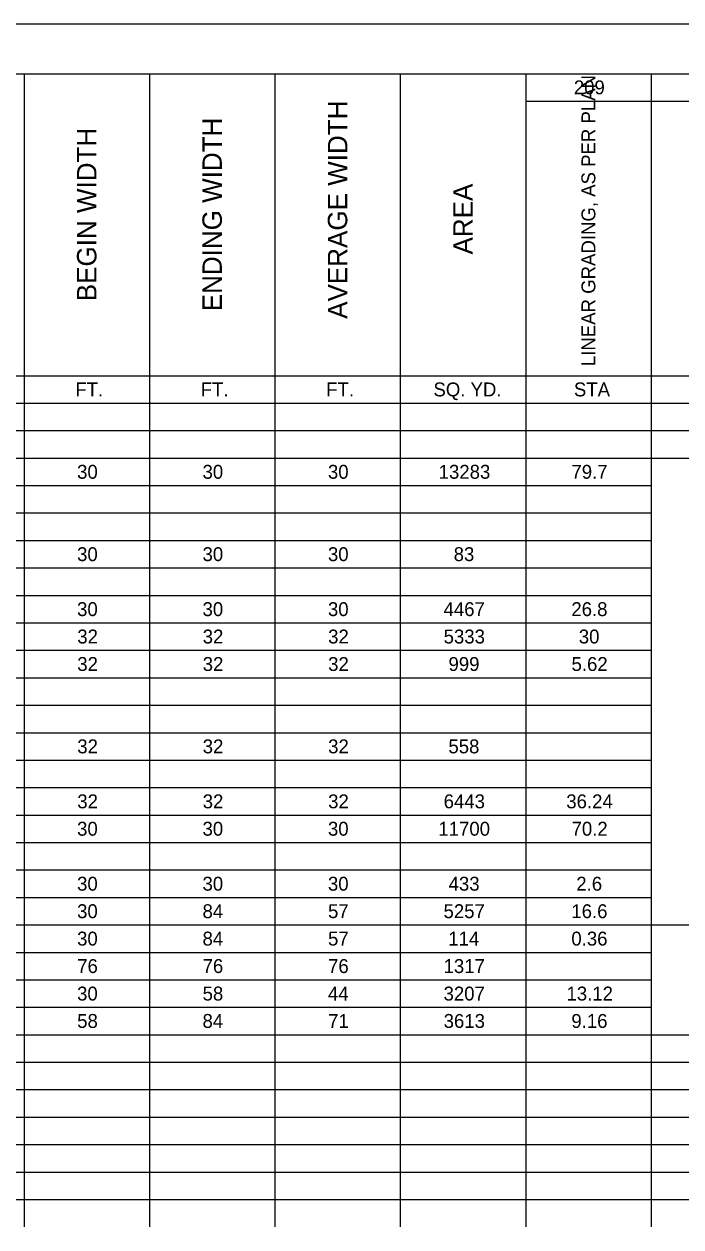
# Model space of a CAD drawing. Extents: x 0 to 34, y 0 to 22.
# Drawn here: x 13.03 to 19.65, y 9.88 to 22 of the extents above; entities that cross this region are included whole.
import ezdxf

# ---------------------------------------------------------------- set-up
doc = ezdxf.new("R2010")
doc.units = 0
for name, color, linetype in [('SH_Border', 7, 'Continuous'), ('SH_Cut_Line', 7, 'Continuous'), ('SH_Text', 7, 'Continuous')]:
    doc.layers.add(name, color=color, linetype=linetype)

msp = doc.modelspace()

# ---------------------------------------------------------------- linework, layer by layer
at = {"layer": 'SH_Border'}
msp.add_lwpolyline([(1.5, 21.5), (33.5, 21.5), (33.5, 0.5), (1.5, 0.5)], close=True, dxfattribs=at)
at = {"layer": 'SH_Cut_Line'}
msp.add_lwpolyline([(0, 0), (34, 0), (34, 22), (0, 22)], close=True, dxfattribs=at)
at = {"layer": 'SH_Text'}
for p, q in [((8.427, 21.5), (13.026, 21.5)), ((13.026, 21.5), (15.556, 21.5)), ((13.026, 21.5), (13.026, 21.223)), ((14.291, 21.5), (14.291, 21.223)), ((15.556, 21.5), (23.145, 21.5)), ((15.556, 21.5), (15.556, 21.223)), ((16.821, 21.5), (16.821, 21.223)), ((18.086, 21.5), (18.086, 21.223)), ((19.351, 21.5), (19.351, 21.223)), ((13.026, 21.223), (13.026, 20.947)), ((14.291, 21.223), (14.291, 20.947)), ((15.556, 21.223), (15.556, 20.947)), ((16.821, 21.223), (16.821, 20.947)), ((18.086, 21.223), (23.145, 21.223)), ((18.086, 21.223), (18.086, 20.947)), ((19.351, 21.223), (19.351, 20.947)), ((13.026, 20.947), (13.026, 20.67)), ((14.291, 20.947), (14.291, 20.67)), ((15.556, 20.947), (15.556, 20.67)), ((16.821, 20.947), (16.821, 20.67)), ((18.086, 20.947), (18.086, 20.67)), ((19.351, 20.947), (19.351, 20.67)), ((13.026, 20.67), (13.026, 20.393)), ((14.291, 20.67), (14.291, 20.393)), ((15.556, 20.67), (15.556, 20.393)), ((16.821, 20.67), (16.821, 20.393)), ((18.086, 20.67), (18.086, 20.393)), ((19.351, 20.67), (19.351, 20.393)), ((13.026, 20.393), (13.026, 20.116)), ((14.291, 20.393), (14.291, 20.116)), ((15.556, 20.393), (15.556, 20.116)), ((16.821, 20.393), (16.821, 20.116)), ((18.086, 20.393), (18.086, 20.116)), ((19.351, 20.393), (19.351, 20.116)), ((13.026, 20.116), (13.026, 19.84)), ((14.291, 20.116), (14.291, 19.84)), ((15.556, 20.116), (15.556, 19.84)), ((16.821, 20.116), (16.821, 19.84)), ((18.086, 20.116), (18.086, 19.84)), ((19.351, 20.116), (19.351, 19.84)), ((13.026, 19.84), (13.026, 19.563)), ((14.291, 19.84), (14.291, 19.563)), ((15.556, 19.84), (15.556, 19.563)), ((16.821, 19.84), (16.821, 19.563)), ((18.086, 19.84), (18.086, 19.563)), ((19.351, 19.84), (19.351, 19.563)), ((13.026, 19.563), (13.026, 19.01)), ((14.291, 19.563), (14.291, 19.01)), ((15.556, 19.563), (15.556, 19.01)), ((16.821, 19.563), (16.821, 19.01)), ((18.086, 19.563), (18.086, 19.01)), ((19.351, 19.563), (19.351, 19.01)), ((13.026, 19.01), (13.026, 18.18)), ((14.291, 19.01), (14.291, 18.18)), ((15.556, 19.01), (15.556, 18.18)), ((16.821, 19.01), (16.821, 18.18)), ((18.086, 19.01), (18.086, 18.18)), ((19.351, 19.01), (19.351, 18.18)), ((11.761, 18.456), (13.026, 18.456)), ((13.026, 18.456), (15.556, 18.456)), ((15.556, 18.456), (23.145, 18.456)), ((8.427, 18.18), (13.026, 18.18)), ((13.026, 18.18), (15.556, 18.18)), ((13.026, 18.18), (13.026, 17.349)), ((14.291, 18.18), (14.291, 17.349)), ((15.556, 18.18), (23.145, 18.18)), ((15.556, 18.18), (15.556, 17.349)), ((16.821, 18.18), (16.821, 17.349)), ((18.086, 18.18), (18.086, 17.349)), ((19.351, 18.18), (19.351, 17.349)), ((8.427, 17.903), (13.026, 17.903)), ((13.026, 17.903), (15.556, 17.903)), ((15.556, 17.903), (23.145, 17.903)), ((8.427, 17.626), (13.026, 17.626)), ((13.026, 17.626), (15.556, 17.626)), ((15.556, 17.626), (23.145, 17.626)), ((8.427, 17.349), (13.026, 17.349)), ((13.026, 17.349), (15.556, 17.349)), ((13.026, 17.349), (13.026, 17.073)), ((14.291, 17.349), (14.291, 17.073)), ((15.556, 17.349), (19.351, 17.349)), ((15.556, 17.349), (15.556, 17.073)), ((16.821, 17.349), (16.821, 17.073)), ((18.086, 17.349), (18.086, 17.073)), ((19.351, 17.349), (19.351, 17.073)), ((8.427, 17.073), (13.026, 17.073)), ((13.026, 17.073), (15.556, 17.073)), ((13.026, 17.073), (13.026, 15.966)), ((14.291, 17.073), (14.291, 15.966)), ((15.556, 17.073), (19.351, 17.073)), ((15.556, 17.073), (15.556, 15.966)), ((16.821, 17.073), (16.821, 15.966)), ((18.086, 17.073), (18.086, 15.966)), ((19.351, 17.073), (19.351, 15.966)), ((8.427, 16.796), (13.026, 16.796)), ((13.026, 16.796), (15.556, 16.796)), ((15.556, 16.796), (19.351, 16.796)), ((8.427, 16.519), (13.026, 16.519)), ((13.026, 16.519), (15.556, 16.519)), ((15.556, 16.519), (19.351, 16.519)), ((8.427, 16.243), (13.026, 16.243)), ((13.026, 16.243), (15.556, 16.243)), ((15.556, 16.243), (19.351, 16.243)), ((8.427, 15.966), (13.026, 15.966)), ((13.026, 15.966), (15.556, 15.966)), ((13.026, 15.966), (13.026, 15.689)), ((14.291, 15.966), (14.291, 15.689)), ((15.556, 15.966), (19.351, 15.966)), ((15.556, 15.966), (15.556, 15.689)), ((16.821, 15.966), (16.821, 15.689)), ((18.086, 15.966), (18.086, 15.689)), ((19.351, 15.966), (19.351, 15.689)), ((8.427, 15.689), (13.026, 15.689)), ((13.026, 15.689), (15.556, 15.689)), ((13.026, 15.689), (13.026, 15.136)), ((14.291, 15.689), (14.291, 15.136)), ((15.556, 15.689), (19.351, 15.689)), ((15.556, 15.689), (15.556, 15.136)), ((16.821, 15.689), (16.821, 15.136)), ((18.086, 15.689), (18.086, 15.136)), ((19.351, 15.689), (19.351, 15.136)), ((8.427, 15.412), (13.026, 15.412)), ((13.026, 15.412), (15.556, 15.412)), ((15.556, 15.412), (19.351, 15.412)), ((8.427, 15.136), (13.026, 15.136)), ((13.026, 15.136), (15.556, 15.136)), ((13.026, 15.136), (13.026, 14.582)), ((14.291, 15.136), (14.291, 14.582)), ((15.556, 15.136), (19.351, 15.136)), ((15.556, 15.136), (15.556, 14.582)), ((16.821, 15.136), (16.821, 14.582)), ((18.086, 15.136), (18.086, 14.582)), ((19.351, 15.136), (19.351, 14.582)), ((8.427, 14.859), (13.026, 14.859)), ((13.026, 14.859), (15.556, 14.859)), ((15.556, 14.859), (19.351, 14.859)), ((8.427, 14.582), (13.026, 14.582)), ((13.026, 14.582), (15.556, 14.582)), ((13.026, 14.582), (13.026, 14.306)), ((14.291, 14.582), (14.291, 14.306)), ((15.556, 14.582), (19.351, 14.582)), ((15.556, 14.582), (15.556, 14.306)), ((16.821, 14.582), (16.821, 14.306)), ((18.086, 14.582), (18.086, 14.306)), ((19.351, 14.582), (19.351, 14.306)), ((8.427, 14.306), (13.026, 14.306)), ((13.026, 14.306), (15.556, 14.306)), ((13.026, 14.306), (13.026, 13.752)), ((14.291, 14.306), (14.291, 13.752)), ((15.556, 14.306), (19.351, 14.306)), ((15.556, 14.306), (15.556, 13.752)), ((16.821, 14.306), (16.821, 13.752)), ((18.086, 14.306), (18.086, 13.752)), ((19.351, 14.306), (19.351, 13.752)), ((8.427, 14.029), (13.026, 14.029)), ((13.026, 14.029), (15.556, 14.029)), ((15.556, 14.029), (19.351, 14.029)), ((8.427, 13.752), (13.026, 13.752)), ((13.026, 13.752), (15.556, 13.752)), ((13.026, 13.752), (13.026, 13.476)), ((14.291, 13.752), (14.291, 13.476)), ((15.556, 13.752), (19.351, 13.752)), ((15.556, 13.752), (15.556, 13.476)), ((16.821, 13.752), (16.821, 13.476)), ((18.086, 13.752), (18.086, 13.476)), ((19.351, 13.752), (19.351, 13.476)), ((8.427, 13.476), (13.026, 13.476)), ((13.026, 13.476), (15.556, 13.476)), ((13.026, 13.476), (13.026, 12.645)), ((14.291, 13.476), (14.291, 12.645)), ((15.556, 13.476), (19.351, 13.476)), ((15.556, 13.476), (15.556, 12.645)), ((16.821, 13.476), (16.821, 12.645)), ((18.086, 13.476), (18.086, 12.645)), ((19.351, 13.476), (19.351, 12.645)), ((8.427, 13.199), (13.026, 13.199)), ((13.026, 13.199), (15.556, 13.199)), ((15.556, 13.199), (19.351, 13.199)), ((8.427, 12.922), (13.026, 12.922)), ((13.026, 12.922), (15.556, 12.922)), ((15.556, 12.922), (23.145, 12.922)), ((8.427, 12.645), (13.026, 12.645)), ((13.026, 12.645), (15.556, 12.645)), ((13.026, 12.645), (13.026, 12.369)), ((14.291, 12.645), (14.291, 12.369)), ((15.556, 12.645), (19.351, 12.645)), ((15.556, 12.645), (15.556, 12.369)), ((16.821, 12.645), (16.821, 12.369)), ((18.086, 12.645), (18.086, 12.369)), ((19.351, 12.645), (19.351, 12.369)), ((8.427, 12.369), (13.026, 12.369)), ((13.026, 12.369), (15.556, 12.369)), ((13.026, 12.369), (13.026, 12.092)), ((14.291, 12.369), (14.291, 12.092)), ((15.556, 12.369), (19.351, 12.369)), ((15.556, 12.369), (15.556, 12.092)), ((16.821, 12.369), (16.821, 12.092)), ((18.086, 12.369), (18.086, 12.092)), ((19.351, 12.369), (19.351, 12.092)), ((8.427, 12.092), (13.026, 12.092)), ((13.026, 12.092), (15.556, 12.092)), ((13.026, 12.092), (13.026, 11.262)), ((14.291, 12.092), (14.291, 11.262)), ((15.556, 12.092), (19.351, 12.092)), ((15.556, 12.092), (15.556, 11.262)), ((16.821, 12.092), (16.821, 11.262)), ((18.086, 12.092), (18.086, 11.262)), ((19.351, 12.092), (19.351, 11.262)), ((8.427, 11.815), (13.026, 11.815)), ((13.026, 11.815), (15.556, 11.815)), ((15.556, 11.815), (23.145, 11.815)), ((8.427, 11.539), (13.026, 11.539)), ((13.026, 11.539), (15.556, 11.539)), ((15.556, 11.539), (23.145, 11.539)), ((8.427, 11.262), (13.026, 11.262)), ((13.026, 11.262), (15.556, 11.262)), ((13.026, 11.262), (13.026, 10.708)), ((14.291, 11.262), (14.291, 10.708)), ((15.556, 11.262), (23.145, 11.262)), ((15.556, 11.262), (15.556, 10.708)), ((16.821, 11.262), (16.821, 10.708)), ((18.086, 11.262), (18.086, 10.708)), ((19.351, 11.262), (19.351, 10.708)), ((8.427, 10.985), (13.026, 10.985)), ((13.026, 10.985), (15.556, 10.985)), ((15.556, 10.985), (23.145, 10.985)), ((8.427, 10.708), (13.026, 10.708)), ((13.026, 10.708), (15.556, 10.708)), ((13.026, 10.708), (13.026, 9.878)), ((14.291, 10.708), (14.291, 9.878)), ((15.556, 10.708), (23.145, 10.708)), ((15.556, 10.708), (15.556, 9.878)), ((16.821, 10.708), (16.821, 9.878)), ((18.086, 10.708), (18.086, 9.878)), ((19.351, 10.708), (19.351, 9.878)), ((8.427, 10.432), (13.026, 10.432)), ((13.026, 10.432), (15.556, 10.432)), ((15.556, 10.432), (23.145, 10.432)), ((8.427, 10.155), (13.026, 10.155)), ((13.026, 10.155), (15.556, 10.155)), ((15.556, 10.155), (23.145, 10.155))]:
    msp.add_line(p, q, dxfattribs=at)

# ---------------------------------------------------------------- texts
for s, height, p in [('LINEAR GRADING, AS PER PLAN', 0.14, (18.788, 18.553)), ('AVERAGE WIDTH', 0.196, (16.286, 19.03)), ('ENDING WIDTH', 0.196, (15.021, 19.106)), ('BEGIN WIDTH', 0.196, (13.756, 19.207)), ('AREA', 0.196, (17.551, 19.678))]:
    msp.add_text(s, height=height, rotation=90, dxfattribs=at).set_placement(p)
for s, p in [('209', (18.571, 21.292)), ('FT.', (13.543, 18.248)), ('FT.', (14.808, 18.248)), ('FT.', (16.073, 18.248)), ('SQ. YD.', (17.155, 18.248)), ('STA', (18.572, 18.248)), ('30', (13.561, 17.418)), ('30', (14.826, 17.418)), ('30', (16.091, 17.418)), ('13283', (17.208, 17.418)), ('79.7', (18.547, 17.418)), ('30', (13.561, 16.588)), ('30', (14.826, 16.588)), ('30', (16.091, 16.588)), ('83', (17.359, 16.588)), ('30', (13.561, 16.034)), ('30', (14.826, 16.034)), ('30', (16.091, 16.034)), ('4467', (17.257, 16.034)), ('26.8', (18.546, 16.034)), ('32', (13.563, 15.758)), ('32', (14.828, 15.758)), ('32', (16.093, 15.758)), ('5333', (17.258, 15.758)), ('30', (18.621, 15.758)), ('32', (13.563, 15.481)), ('32', (14.828, 15.481)), ('32', (16.093, 15.481)), ('999', (17.307, 15.481)), ('5.62', (18.548, 15.481)), ('32', (13.563, 14.651)), ('32', (14.828, 14.651)), ('32', (16.093, 14.651)), ('558', (17.306, 14.651)), ('32', (13.563, 14.097)), ('32', (14.828, 14.097)), ('32', (16.093, 14.097)), ('6443', (17.258, 14.097)), ('36.24', (18.495, 14.097)), ('30', (13.561, 13.821)), ('30', (14.826, 13.821)), ('30', (16.091, 13.821)), ('11700', (17.205, 13.821)), ('70.2', (18.548, 13.821)), ('30', (13.561, 13.267)), ('30', (14.826, 13.267)), ('30', (16.091, 13.267)), ('433', (17.308, 13.267)), ('2.6', (18.596, 13.267)), ('30', (13.561, 12.99)), ('84', (14.826, 12.99)), ('57', (16.092, 12.99)), ('5257', (17.257, 12.99)), ('16.6', (18.546, 12.99)), ('30', (13.561, 12.714)), ('84', (14.826, 12.714)), ('57', (16.092, 12.714)), ('114', (17.305, 12.714)), ('0.36', (18.546, 12.714)), ('76', (13.562, 12.437)), ('76', (14.827, 12.437)), ('76', (16.092, 12.437)), ('1317', (17.257, 12.437)), ('30', (13.561, 12.16)), ('58', (14.827, 12.16)), ('44', (16.091, 12.16)), ('3207', (17.257, 12.16)), ('13.12', (18.497, 12.16)), ('58', (13.562, 11.884)), ('84', (14.826, 11.884)), ('71', (16.093, 11.884)), ('3613', (17.258, 11.884)), ('9.16', (18.546, 11.884))]:
    msp.add_text(s, height=0.14, dxfattribs=at).set_placement(p)

doc.saveas('drawing.dxf')
